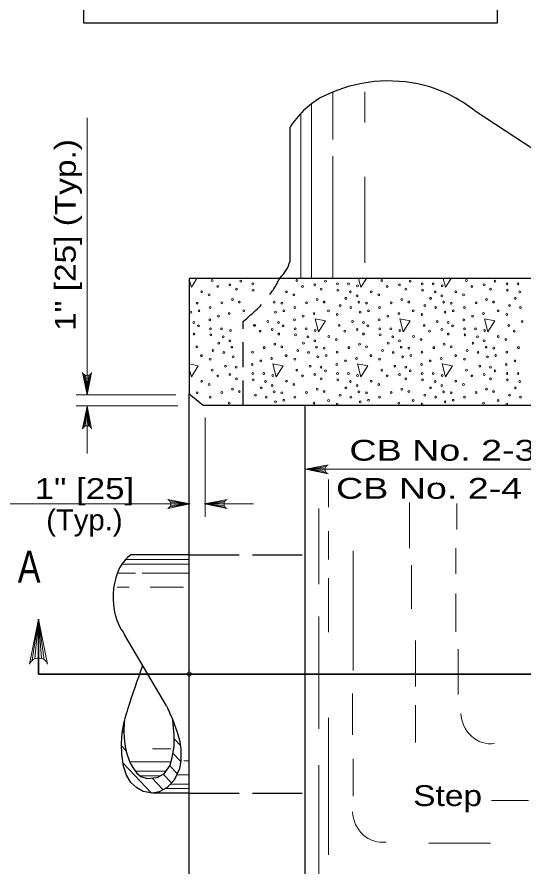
# Model space of a CAD drawing. Extents: x 1083.1 to 1117.1, y 697.4 to 719.4.
# Drawn here: x 1099.92 to 1103.72, y 701.9 to 708.27 of the extents above; entities that cross this region are included whole.
import ezdxf
from ezdxf.enums import TextEntityAlignment as Align

# ---------------------------------------------------------------- set-up
doc = ezdxf.new("R2010")
doc.units = 0
doc.header["$LTSCALE"] = 0.062
doc.header["$PDMODE"] = 32
doc.header["$PDSIZE"] = 0.031
doc.linetypes.add('LONG_DASHED', pattern=[7.5, 6, -1.5])
doc.linetypes.add('MEDIUM_DASHED', pattern=[4.5, 3, -1.5])
doc.layers.add('1', color=7, linetype='Continuous', lineweight=13)

msp = doc.modelspace()

# ---------------------------------------------------------------- linework, layer by layer
at = {"layer": '1'}
for p, q in [((1102.288, 707.35375), (1102.288, 707.709)), ((1102.52808, 707.47992), (1102.52808, 707.709)), ((1102.12792, 706.31208), (1102.12792, 707.62)), ((1102.04792, 706.31208), (1102.04792, 707.54742)), ((1100.44833, 707.515), (1100.44833, 705.439)), ((1102.288, 706.31208), (1102.288, 707.22725)), ((1102.52808, 706.42775), (1102.52808, 707.0735)), ((1101.21358, 705.63333), (1101.22875, 705.5755)), ((1100.427, 705.59133), (1100.44833, 705.439)), ((1100.43758, 705.58617), (1100.44833, 705.439)), ((1100.47192, 705.59308), (1100.44833, 705.439)), ((1100.462, 705.58725), (1100.44833, 705.439)), ((1100.44833, 705.58458), (1100.44833, 705.439)), ((1101.11225, 705.439), (1100.36658, 705.439)), ((1101.12858, 705.35708), (1100.36658, 705.35708)), ((1100.42475, 705.19975), (1100.44833, 705.35383)), ((1100.43467, 705.20558), (1100.44833, 705.35383)), ((1100.44833, 705.35383), (1100.44833, 705.00008)), ((1100.44833, 705.20825), (1100.44833, 705.35383)), ((1100.45908, 705.20667), (1100.44833, 705.35383)), ((1100.46967, 705.20158), (1100.44833, 705.35383)), ((1101.33133, 705.26867), (1101.33133, 704.52492)), ((1102.23642, 704.903), (1102.08417, 704.88167)), ((1102.23125, 704.89242), (1102.08417, 704.88167)), ((1102.08417, 704.88167), (1105.29683, 704.88167)), ((1102.22975, 704.88167), (1102.08417, 704.88167)), ((1102.23242, 704.868), (1102.08417, 704.88167)), ((1102.23825, 704.85808), (1102.08417, 704.88167)), ((1102.25433, 704.59733), (1102.25433, 704.80592)), ((1101.22017, 704.62192), (1099.86925, 704.62192)), ((1101.06608, 704.64542), (1101.22017, 704.62192)), ((1101.06783, 704.60058), (1101.22017, 704.62192)), ((1101.07192, 704.63558), (1101.22017, 704.62192)), ((1101.073, 704.61108), (1101.22017, 704.62192)), ((1101.07458, 704.62192), (1101.22017, 704.62192)), ((1101.48033, 704.64317), (1101.32808, 704.62192)), ((1101.47517, 704.63267), (1101.32808, 704.62192)), ((1101.69433, 704.62192), (1101.32808, 704.62192)), ((1101.47367, 704.62192), (1101.32808, 704.62192)), ((1101.47633, 704.60817), (1101.32808, 704.62192)), ((1101.48217, 704.59833), (1101.32808, 704.62192)), ((1102.86275, 704.29), (1102.86275, 704.63233)), ((1103.21608, 704.43), (1103.21608, 704.62475)), ((1102.18375, 704.02183), (1102.18375, 704.58867)), ((1102.25433, 704.206), (1102.25433, 704.418)), ((1103.2085, 704.09867), (1103.2085, 704.29)), ((1102.43942, 703.37508), (1102.43942, 704.27133)), ((1101.2135, 704.17158), (1100.709, 704.17158)), ((1101.2135, 704.20608), (1100.737, 704.20608)), ((1102.87667, 704.16417), (1102.87667, 703.83533)), ((1100.81175, 704.10233), (1100.67467, 704.10233)), ((1101.2135, 704.10233), (1100.86058, 704.10233)), ((1102.25433, 703.66125), (1102.25433, 704.066)), ((1100.763, 703.99842), (1100.67467, 703.99842)), ((1101.16883, 703.99842), (1100.91975, 703.99842)), ((1103.2085, 703.6645), (1103.2085, 703.94992)), ((1102.18375, 702.93633), (1102.18375, 703.77867)), ((1100.03825, 703.45042), (1100.08533, 703.75858)), ((1100.058, 703.46208), (1100.08533, 703.75858)), ((1100.08533, 703.4675), (1100.08533, 703.75858)), ((1100.10692, 703.46433), (1100.08533, 703.75858)), ((1100.128, 703.454), (1100.08533, 703.75858)), ((1102.90675, 703.2545), (1102.90675, 703.59917)), ((1103.22492, 703.19408), (1103.22492, 703.53383)), ((1102.43508, 702.89133), (1102.43508, 703.20192)), ((1102.90675, 702.83367), (1102.90675, 703.11442)), ((1102.25433, 701.99342), (1102.25433, 703.01817)), ((1100.72517, 702.959), (1100.72192, 702.96242)), ((1101.09133, 702.99775), (1101.08983, 702.99917)), ((1101.09675, 702.98308), (1101.09092, 702.98942)), ((1100.72275, 702.90908), (1100.714, 702.9185)), ((1100.72258, 702.91283), (1100.71458, 702.92142)), ((1100.72258, 702.91142), (1100.72892, 702.84275)), ((1101.14642, 702.813), (1101.09983, 702.86233)), ((1100.74167, 702.77183), (1100.70733, 702.80817)), ((1101.07575, 702.78767), (1100.93883, 702.78767)), ((1101.149, 702.69283), (1101.09133, 702.754)), ((1101.15083, 702.78725), (1101.15042, 702.7015)), ((1101.07792, 702.68958), (1100.76725, 702.68958)), ((1101.2135, 702.69625), (1101.17158, 702.69625)), ((1102.43942, 702.43225), (1102.43942, 702.71225)), ((1100.92925, 702.45592), (1100.71725, 702.68008)), ((1101.12367, 702.60217), (1101.06858, 702.6605)), ((1102.18375, 701.68542), (1102.18375, 702.66567)), ((1101.04025, 702.62042), (1100.8095, 702.62042)), ((1100.99742, 702.58583), (1100.84317, 702.58583)), ((1101.016, 702.48125), (1100.9335, 702.56858)), ((1101.07992, 702.53133), (1101.01742, 702.59733)), ((1101.2135, 702.5925), (1101.11933, 702.5925)), ((1101.2135, 702.52325), (1101.07183, 702.52325)), ((1100.8685, 702.4675), (1100.8205, 702.49575)), ((1101.2135, 702.48867), (1101.02925, 702.48867)), ((1103.75192, 702.40033), (1103.475, 702.40033)), ((1103.0065, 702.08125), (1103.46758, 702.08125))]:
    msp.add_line(p, q, dxfattribs=at)
at = {"layer": '1', "lineweight": 25}
for p, q in [((1104.58683, 706.756), (1103.35975, 707.5605)), ((1101.96792, 706.44075), (1101.96792, 707.44667)), ((1101.2135, 706.31208), (1101.2135, 705.44767)), ((1101.2135, 701.176), (1101.2135, 705.44767)), ((1102.08108, 701.25917), (1102.08108, 705.36217)), ((1101.2135, 704.24067), (1100.776, 704.24067)), ((1101.04225, 703.10833), (1100.732, 703.639)), ((1100.72683, 702.98875), (1100.72258, 702.91142)), ((1101.14017, 702.85133), (1101.15083, 702.78725)), ((1100.8205, 702.49575), (1100.776, 702.53433)), ((1101.2135, 702.45408), (1100.93825, 702.45408))]:
    msp.add_line(p, q, dxfattribs=at)
at = {"layer": '1', "linetype": 'MEDIUM_DASHED', "lineweight": 25}
msp.add_line((1101.61742, 705.36217), (1101.61742, 705.99), dxfattribs=at)
at = {"layer": '1', "linetype": 'LONG_DASHED', "lineweight": 25}
for p, q in [((1101.2135, 704.24067), (1102.08108, 704.24067)), ((1101.2135, 702.45408), (1102.08108, 702.45408))]:
    msp.add_line(p, q, dxfattribs=at)
at = {"layer": '1', "lineweight": 35}
for p, q in [((1100.08533, 703.75858), (1100.08533, 703.34742)), ((1100.08533, 703.34742), (1104.89842, 703.34742))]:
    msp.add_line(p, q, dxfattribs=at)
at = {"layer": '1', "lineweight": 25}
msp.add_lwpolyline([(1100.42325, 708.79667), (1103.51875, 708.79667), (1103.51875, 708.2245), (1100.42325, 708.2245)], close=True, dxfattribs=at)
for points in [[(1106.86575, 705.43083), (1106.86575, 706.31208), (1101.2135, 706.31208)], [(1101.2135, 705.44708), (1101.31708, 705.36217), (1106.77217, 705.36217)], [(1101.08958, 703.00258), (1101.12342, 702.91108), (1101.14017, 702.85133), (1101.15083, 702.78725), (1101.15042, 702.7015), (1101.13958, 702.63625), (1101.10025, 702.55125), (1101.04667, 702.49833), (1100.98692, 702.46508), (1100.93825, 702.45408), (1100.8685, 702.4675), (1100.8205, 702.49575), (1100.776, 702.53433), (1100.74242, 702.58867), (1100.72017, 702.65692), (1100.709, 702.74575), (1100.70667, 702.82517), (1100.71192, 702.90675), (1100.72683, 702.98875)], [(1100.709, 702.74575), (1100.70667, 702.82517), (1100.71192, 702.90675), (1100.72683, 702.98875), (1100.72258, 702.91142), (1100.72892, 702.84275), (1100.73658, 702.79033), (1100.74925, 702.74317), (1100.77092, 702.67858), (1100.795, 702.63942), (1100.8205, 702.60575), (1100.85108, 702.57892), (1100.89683, 702.56533), (1100.97317, 702.57217), (1101.02792, 702.60308), (1101.07108, 702.66367), (1101.08633, 702.7215), (1101.099, 702.80367), (1101.10042, 702.88858), (1101.08958, 703.00258)], [(1101.099, 702.80367), (1101.10042, 702.88858), (1101.08958, 703.00258)], [(1100.72892, 702.84275), (1100.73658, 702.79033), (1100.74925, 702.74317), (1100.77092, 702.67858)], [(1101.15042, 702.7015), (1101.13958, 702.63625), (1101.10025, 702.55125), (1101.04667, 702.49833), (1100.98692, 702.46508), (1100.93825, 702.45408), (1100.8685, 702.4675)], [(1100.85108, 702.57892), (1100.89683, 702.56533), (1100.97317, 702.57217)]]:
    msp.add_lwpolyline(points, dxfattribs=at)
at = {"layer": '1'}
for points in [[(1101.2135, 706.30517), (1101.22875, 706.24717), (1101.27, 706.31208)], [(1102.4805, 706.31208), (1102.49758, 706.24717), (1102.53883, 706.31208)], [(1103.11492, 706.31217), (1103.132, 706.24717), (1103.17325, 706.31208)], [(1101.22875, 705.5755), (1101.281, 705.65767), (1101.21358, 705.67083)], [(1100.482, 705.60725), (1100.44833, 705.439), (1100.41467, 705.60725)], [(1100.41467, 705.18558), (1100.44833, 705.35383), (1100.482, 705.18558)], [(1102.25233, 704.848), (1102.08417, 704.88167), (1102.25233, 704.91533)], [(1101.05192, 704.6555), (1101.22017, 704.62192), (1101.05192, 704.58825)], [(1101.49625, 704.58825), (1101.32808, 704.62192), (1101.49625, 704.6555)], [(1100.01808, 703.42217), (1100.08533, 703.75858), (1100.15267, 703.42217)], [(1101.08958, 703.00258), (1101.12342, 702.91108), (1101.14017, 702.85133)], [(1100.97317, 702.57217), (1101.02792, 702.60308), (1101.07108, 702.66367), (1101.08633, 702.7215), (1101.099, 702.80367)], [(1100.776, 702.53433), (1100.74242, 702.58867), (1100.72017, 702.65692), (1100.709, 702.74575)], [(1100.77092, 702.67858), (1100.795, 702.63942), (1100.8205, 702.60575), (1100.85108, 702.57892)]]:
    msp.add_lwpolyline(points, dxfattribs=at)
for points in [[(1102.15475, 706.00867), (1102.18033, 705.91142), (1102.23258, 705.99358)], [(1102.78908, 706.00867), (1102.81475, 705.91142), (1102.867, 705.99358)], [(1103.42358, 706.00867), (1103.44917, 705.91142), (1103.50142, 705.99358)], [(1101.8375, 705.67292), (1101.86317, 705.5755), (1101.91542, 705.65767)], [(1102.47192, 705.67292), (1102.49758, 705.5755), (1102.54975, 705.65767)], [(1103.10633, 705.67292), (1103.132, 705.5755), (1103.18417, 705.65767)]]:
    msp.add_lwpolyline(points, close=True, dxfattribs=at)
for centre, radius, start, end in [((1100.44829, 705.62081), 0.03631, 202.08782, 337.91395), ((1100.44837, 705.17204), 0.03631, 22.08782, 157.91395), ((1102.26595, 704.88169), 0.03631, 112.08782, 247.91395), ((1101.03834, 704.62184), 0.03631, 292.08782, 67.91395), ((1101.50988, 704.62192), 0.03631, 112.08782, 247.91395), ((1100.08545, 703.395), 0.07261, 22.08782, 157.91395)]:
    msp.add_arc(centre, radius, start, end, dxfattribs=at)
at = {"layer": '1', "lineweight": 25}
for centre, major_axis, start_param, end_param in [((1102.70511, 706.57157), (0, 1.22024), 6.0913628, 6.7427401), ((1102.72308, 706.68796), (0, 1.10248), 5.6254463, 6.0881824), ((1102.53847, 707.02575), (0, 0.7362), 0.5184487, 0.9622613), ((1101.71591, 706.52373), (0, 0.27941), 3.8810657, 4.4108036), ((1100.93823, 703.99401), (0, 0.30064), 0.608535, 1.0523476), ((1101.11342, 703.92196), (0, -0.49832), 4.2528342, 4.9042115), ((1101.06853, 703.91419), (0, -0.45022), 4.9073919, 5.370128)]:
    msp.add_ellipse(centre, major_axis=major_axis, ratio=0.944544, start_param=start_param, end_param=end_param, dxfattribs=at)
at = {"layer": '1'}
for centre in [(1101.38476, 706.29609), (1101.42589, 706.25254), (1101.51751, 706.26435), (1101.59861, 706.29156), (1101.68853, 706.27068), (1102.01916, 706.29609), (1102.06029, 706.25254), (1102.15191, 706.26435), (1102.23301, 706.29156), (1102.32294, 706.27068), (1102.4052, 706.27068), (1102.47281, 706.25708), (1102.65357, 706.29609), (1102.6947, 706.25254), (1102.78631, 706.26435), (1102.86741, 706.29156), (1102.95734, 706.27068), (1103.0396, 706.27068), (1103.10722, 706.25708), (1103.28797, 706.29609), (1103.3291, 706.25254), (1103.42072, 706.26435), (1103.50181, 706.29156), (1103.59174, 706.27068), (1103.674, 706.27068), (1101.30594, 706.21264), (1101.36245, 706.18907), (1101.56578, 706.23139), (1101.69107, 706.22445), (1101.94034, 706.21264), (1101.99685, 706.18907), (1102.20018, 706.23139), (1102.32547, 706.22445), (1102.41889, 706.21085), (1102.57474, 706.21264), (1102.63126, 706.18907), (1102.83458, 706.23139), (1102.95988, 706.22445), (1103.05329, 706.21085), (1103.20914, 706.21264), (1103.26566, 706.18907), (1103.46898, 706.23139), (1103.59428, 706.22445), (1103.68769, 706.21085), (1101.27168, 706.12555), (1101.45698, 706.12896), (1101.5358, 706.15432), (1101.58804, 706.13529), (1101.84872, 706.13377), (1101.90608, 706.12555), (1102.09138, 706.12896), (1102.1702, 706.15432), (1102.22244, 706.13529), (1102.38543, 706.16277), (1102.46938, 706.1809), (1102.48312, 706.13377), (1102.54048, 706.12555), (1102.72578, 706.12896), (1102.80461, 706.15432), (1102.85684, 706.13529), (1103.01983, 706.16277), (1103.10378, 706.1809), (1103.11753, 706.13377), (1103.17489, 706.12555), (1103.36018, 706.12896), (1103.43901, 706.15432), (1103.49124, 706.13529), (1103.65423, 706.16277), (1101.22452, 706.05939), (1101.28622, 706.0703), (1101.36932, 706.09471), (1101.62139, 706.06907), (1101.85892, 706.05939), (1101.92062, 706.0703), (1102.00373, 706.09471), (1102.2558, 706.06907), (1102.34234, 706.10808), (1102.42312, 706.09387), (1102.49333, 706.05939), (1102.55502, 706.0703), (1102.63813, 706.09471), (1102.8902, 706.06907), (1102.97674, 706.10808), (1103.05752, 706.09387), (1103.12773, 706.05939), (1103.18942, 706.0703), (1103.27253, 706.09471), (1103.5246, 706.06907), (1103.61114, 706.10808), (1103.69192, 706.09387), (1101.36621, 706.00196), (1101.43123, 706.02917), (1101.51265, 706.0482), (1102.00061, 706.00196), (1102.06563, 706.02917), (1102.14705, 706.0482), (1102.32093, 706.04187), (1102.63501, 706.00196), (1102.70004, 706.02917), (1102.78145, 706.0482), (1102.95533, 706.04187), (1103.26941, 706.00196), (1103.33444, 706.02917), (1103.41585, 706.0482), (1103.58973, 706.04187), (1101.24773, 705.98232), (1101.28141, 705.95573), (1101.37133, 705.93485), (1101.45359, 705.93485), (1101.8013, 705.98931), (1101.88213, 705.98232), (1101.91581, 705.95573), (1102.00574, 705.93485), (1102.088, 705.93485), (1102.33637, 705.96027), (1102.4357, 705.98931), (1102.51654, 705.98232), (1102.55021, 705.95573), (1102.64014, 705.93485), (1102.7224, 705.93485), (1102.97077, 705.96027), (1103.0701, 705.98931), (1103.15094, 705.98232), (1103.18461, 705.95573), (1103.27454, 705.93485), (1103.3568, 705.93485), (1103.60517, 705.96027), (1103.70451, 705.98931), (1101.24858, 705.89556), (1101.37387, 705.88862), (1101.46729, 705.87502), (1101.52121, 705.92125), (1101.74309, 705.91672), (1101.83471, 705.92853), (1101.88298, 705.89556), (1102.00827, 705.88862), (1102.10169, 705.87502), (1102.15561, 705.92125), (1102.25754, 705.87681), (1102.3775, 705.91672), (1102.46911, 705.92853), (1102.51738, 705.89556), (1102.64268, 705.88862), (1102.73609, 705.87502), (1102.79002, 705.92125), (1102.89194, 705.87681), (1103.0119, 705.91672), (1103.10352, 705.92853), (1103.15178, 705.89556), (1103.27708, 705.88862), (1103.37049, 705.87502), (1103.42442, 705.92125), (1103.52634, 705.87681), (1103.6463, 705.91672), (1101.43382, 705.82694), (1101.51778, 705.84508), (1101.853, 705.81849), (1102.06822, 705.82694), (1102.15218, 705.84508), (1102.31406, 705.85325), (1102.48741, 705.81849), (1102.70263, 705.82694), (1102.78658, 705.84508), (1102.94846, 705.85325), (1103.12181, 705.81849), (1103.33703, 705.82694), (1103.42098, 705.84508), (1103.58286, 705.85325), (1101.27083, 705.79946), (1101.39074, 705.77226), (1101.47152, 705.75804), (1101.53152, 705.79795), (1101.68653, 705.75888), (1101.77418, 705.79314), (1101.90524, 705.79946), (1102.02514, 705.77226), (1102.10592, 705.75804), (1102.16592, 705.79795), (1102.22328, 705.78972), (1102.32093, 705.75888), (1102.40858, 705.79314), (1102.53964, 705.79946), (1102.65954, 705.77226), (1102.74032, 705.75804), (1102.80032, 705.79795), (1102.85769, 705.78972), (1102.95533, 705.75888), (1103.04298, 705.79314), (1103.17404, 705.79946), (1103.29394, 705.77226), (1103.37472, 705.75804), (1103.43473, 705.79795), (1103.49209, 705.78972), (1103.58973, 705.75888), (1103.67739, 705.79314), (1101.30419, 705.73325), (1101.36932, 705.70605), (1101.54172, 705.72356), (1101.74843, 705.69334), (1101.82985, 705.71237), (1101.9386, 705.73325), (1102.00373, 705.70605), (1102.17613, 705.72356), (1102.23782, 705.73448), (1102.38284, 705.69334), (1102.46425, 705.71237), (1102.573, 705.73325), (1102.63813, 705.70605), (1102.81053, 705.72356), (1102.87222, 705.73448), (1103.01724, 705.69334), (1103.09865, 705.71237), (1103.2074, 705.73325), (1103.27253, 705.70605), (1103.44493, 705.72356), (1103.50663, 705.73448), (1103.65164, 705.69334), (1101.38476, 705.62444), (1101.4841, 705.65349), (1101.56493, 705.64649), (1101.68341, 705.66614), (1102.01916, 705.62444), (1102.1185, 705.65349), (1102.19933, 705.64649), (1102.23301, 705.61991), (1102.31781, 705.66614), (1102.65357, 705.62444), (1102.7529, 705.65349), (1102.83374, 705.64649), (1102.86741, 705.61991), (1102.95221, 705.66614), (1103.28797, 705.62444), (1103.38731, 705.65349), (1103.46814, 705.64649), (1103.50181, 705.61991), (1103.58661, 705.66614), (1101.42589, 705.5809), (1101.51751, 705.59271), (1101.56578, 705.55974), (1101.68853, 705.59903), (1101.69107, 705.5528), (1101.7708, 705.59903), (1101.83841, 705.58543), (1102.06029, 705.5809), (1102.15191, 705.59271), (1102.20018, 705.55974), (1102.32294, 705.59903), (1102.32547, 705.5528), (1102.4052, 705.59903), (1102.47281, 705.58543), (1102.6947, 705.5809), (1102.78631, 705.59271), (1102.83458, 705.55974), (1102.95734, 705.59903), (1102.95988, 705.5528), (1103.0396, 705.59903), (1103.10722, 705.58543), (1103.3291, 705.5809), (1103.42072, 705.59271), (1103.46898, 705.55974), (1103.59174, 705.59903), (1103.59428, 705.5528), (1103.674, 705.59903), (1101.30594, 705.54099), (1101.36245, 705.51742), (1101.75102, 705.49112), (1101.78449, 705.5392), (1101.83498, 705.50925), (1101.94034, 705.54099), (1101.99685, 705.51742), (1102.38543, 705.49112), (1102.41889, 705.5392), (1102.46938, 705.50925), (1102.57474, 705.54099), (1102.63126, 705.51742), (1103.01983, 705.49112), (1103.05329, 705.5392), (1103.10378, 705.50925), (1103.20914, 705.54099), (1103.26566, 705.51742), (1103.65423, 705.49112), (1103.68769, 705.5392), (1101.27168, 705.4539), (1101.36932, 705.42306), (1101.45698, 705.45731), (1101.5358, 705.48267), (1101.58804, 705.46364), (1101.70794, 705.43643), (1101.78872, 705.42222), (1101.84872, 705.46213), (1101.90608, 705.4539), (1102.00373, 705.42306), (1102.09138, 705.45731), (1102.1702, 705.48267), (1102.22244, 705.46364), (1102.34234, 705.43643), (1102.42312, 705.42222), (1102.48312, 705.46213), (1102.54048, 705.4539), (1102.63813, 705.42306), (1102.72578, 705.45731), (1102.80461, 705.48267), (1102.85684, 705.46364), (1102.97674, 705.43643), (1103.05752, 705.42222), (1103.11753, 705.46213), (1103.17489, 705.4539), (1103.27253, 705.42306), (1103.36018, 705.45731), (1103.43901, 705.48267), (1103.49124, 705.46364), (1103.61114, 705.43643), (1103.69192, 705.42222), (1101.51265, 705.37655), (1101.85892, 705.38774), (1101.92062, 705.39865), (1102.14705, 705.37655), (1102.2558, 705.39742), (1102.32093, 705.37022), (1102.49333, 705.38774), (1102.55502, 705.39865), (1102.78145, 705.37655), (1102.8902, 705.39742), (1102.95533, 705.37022), (1103.12773, 705.38774), (1103.18942, 705.39865), (1103.41585, 705.37655), (1103.5246, 705.39742), (1103.58973, 705.37022)]:
    msp.add_ellipse(centre, major_axis=(0, 0.00718), ratio=0.944544, dxfattribs=at)
at = {"layer": '1', "lineweight": 25}
msp.add_ellipse((1101.70196, 705.96027), major_axis=(0, 0.00718), ratio=0.944544, dxfattribs=at)
at = {"layer": '1'}
for centre in [(1103.47111, 703.06181), (1102.65991, 702.32433)]:
    msp.add_ellipse(centre, major_axis=(0, 0.23746), ratio=0.944544, start_param=1.6092515, end_param=3.2607675, dxfattribs=at)
at = {"layer": '1', "linetype": 'MEDIUM_DASHED', "lineweight": 25}
msp.add_spline([(1101.61742, 705.99), (1101.81292, 706.18525), (1101.89375, 706.31725)], degree=3, dxfattribs=at)
at = {"layer": '1', "lineweight": 25}
for points in [[(1100.72683, 702.98875), (1100.74417, 703.06017), (1100.78083, 703.17458), (1100.86367, 703.4075)], [(1101.04225, 703.10833), (1101.06083, 703.0695), (1101.07642, 703.03425), (1101.08958, 703.00258)]]:
    msp.add_open_spline(points, degree=3, dxfattribs=at)
at = {"layer": '1'}
msp.add_point((1101.2135, 703.34742), dxfattribs=at)

# ---------------------------------------------------------------- texts
at = {"layer": '1', "width": 1.2}
msp.add_text('1" [25] (Typ.)', height=0.156, rotation=90, dxfattribs=at).set_placement((1100.36308, 706.63712), align=Align.CENTER)
at = {"layer": '1'}
for s, height, width, p in [('CB No. 2-3 = 3\'-0" [900]', 0.156, 1.35, (1102.412, 704.94625)), ('CB No. 2-4 = 4\'-0" [1200]', 0.156, 1.35, (1102.31192, 704.661)), ('A', 0.24, 0.8, (1099.929, 704.03125)), ('Step', 0.156, 1.2, (1102.88958, 702.35842))]:
    msp.add_text(s, height=height, dxfattribs=dict(at, width=width)).set_placement(p)
for s, width, p in [('1" [25]', 1.25, (1100.42821, 704.65925)), ('(Typ.)', 1.05, (1100.42821, 704.42458))]:
    msp.add_text(s, height=0.156, dxfattribs=dict(at, width=width)).set_placement(p, align=Align.CENTER)

doc.saveas('drawing.dxf')
